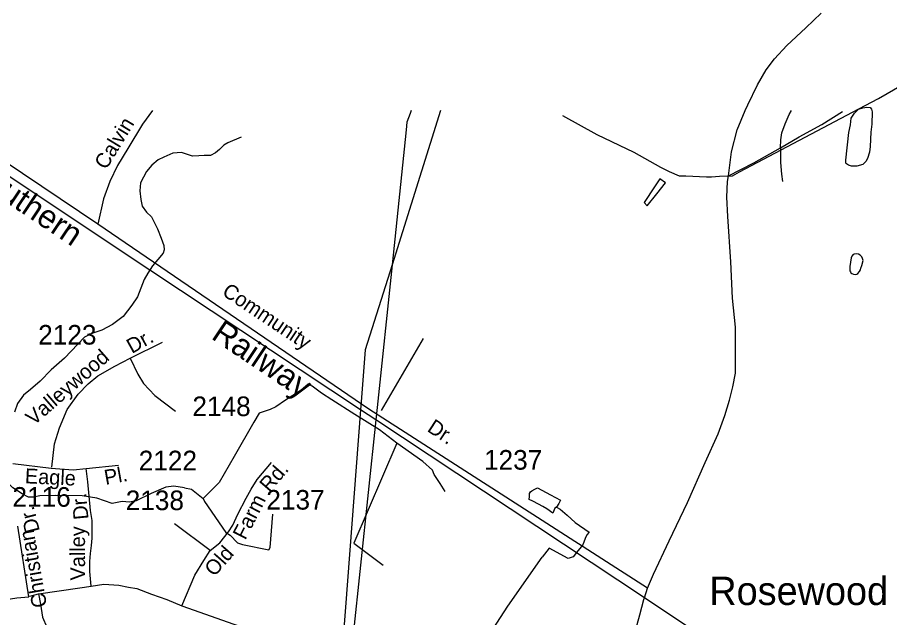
# Model space of a CAD drawing. Extents: x 2260773 to 2342389, y 552869 to 618546.
# Drawn here: x 2273078 to 2278640, y 607521 to 611347 of the extents above; entities that cross this region are included whole.
import ezdxf

# ---------------------------------------------------------------- set-up
doc = ezdxf.new("R2010")
doc.units = 0
for name, color, linetype in [('Exist Boundary Political Urban Extension UEB', 7, 'Continuous'), ('Exist Civil Demographics City Label', 7, 'Continuous'), ('Exist Hydrographic Creek Single Shore', 7, 'Continuous'), ('Exist Hydrographic Misc Water Feature', 7, 'Continuous'), ('Exist Railroad Mainline', 7, 'Continuous'), ('Exist Railroad Mainline Label', 7, 'Continuous'), ('Exist Road Non-System Type 51', 7, 'Continuous'), ('Exist Road Non-System Type 51 Label', 7, 'Continuous'), ('Exist Road Primary NC Attributed', 7, 'Continuous'), ('Exist Road Secondary Type 51 Attributed', 7, 'Continuous'), ('Exist Road Secondary Type 51 Label', 7, 'Continuous'), ('Exist Road Secondary Type 51 Number Label', 7, 'Continuous'), ('Exist Utilities Electrical Transmission Line', 7, 'Continuous')]:
    doc.layers.add(name, color=color, linetype=linetype)

msp = doc.modelspace()

# ---------------------------------------------------------------- linework, layer by layer
at = {"layer": 'Exist Boundary Political Urban Extension UEB'}
for p, q in [((2275776.6, 610753.3), (2275466.5, 609770.2)), ((2275272.2, 608924.2), (2275266.2, 608845.4)), ((2275266.2, 608845.4), (2275143.8, 607237.3))]:
    msp.add_line(p, q, dxfattribs=at)
msp.add_lwpolyline([(2275466.5, 609770.2), (2275295.2, 609227.4), (2275272.2, 608924.2)], dxfattribs=at)
at = {"layer": 'Exist Hydrographic Creek Single Shore'}
msp.add_lwpolyline([(2275482.5, 602914), (2275367.6, 603398.5), (2275023.5, 604563.1), (2274947.7, 604653.2), (2274904.6, 604854.2), (2274802.5, 605059.5), (2274800.7, 605269.5), (2274932.5, 605453.7), (2275188.6, 605665), (2275493.5, 605990.1), (2275598.7, 606128.4), (2275699.6, 606261.3), (2275813.6, 606485.4), (2275951.6, 606863), (2276114.1, 607114.1), (2276154, 607168.5), (2276008.9, 607270.2), (2276088.7, 607411.7), (2276204.8, 607593.2), (2276424.7, 607906.1)], dxfattribs=at)
at = {"layer": 'Exist Hydrographic Misc Water Feature'}
for points in [[(2276553, 610722.8), (2276773.8, 610600.4), (2277009.5, 610487), (2277179.5, 610391.4), (2277233.2, 610364.6), (2277298.9, 610337.7), (2277340.7, 610337.7), (2277471.9, 610331.7), (2277504.7, 610331.7), (2277555.5, 610334.7), (2277639, 610337.7), (2277683.8, 610361.6), (2278444.3, 610764.2), (2278569.1, 610830.5), (2278720.4, 610917.5), (2278843.3, 610982.2), (2278967.3, 611016.2), (2279168.5, 611094.2), (2279279.8, 611127.3), (2279387.7, 611162.2), (2279421.1, 611174.5)], [(2278521.1, 610616.2), (2278515.5, 610524.1), (2278512, 610488.2), (2278498.7, 610448), (2278488.9, 610428), (2278469, 610409.9), (2278431, 610399.4), (2278397, 610399.2), (2278377.1, 610404.7), (2278364.6, 610414.6), (2278360.7, 610418.5), (2278360.7, 610436.7), (2278381, 610612.5), (2278390.2, 610662.7), (2278396, 610704.7), (2278415.9, 610737), (2278441.5, 610761.2), (2278469.6, 610771.5), (2278495.4, 610775.7), (2278515.5, 610771.9), (2278525.4, 610761.9), (2278529.7, 610744.2), (2278526.4, 610666), (2278521.1, 610616.2)], [(2274503.7, 610584.6), (2274420.3, 610547.7), (2274394, 610533.4), (2274366.4, 610505.1), (2274340.5, 610483), (2274308.5, 610466.8), (2274269, 610466.2), (2274234.5, 610464.1), (2274193.3, 610463.5), (2274123, 610485), (2274068.8, 610482.2), (2274011, 610455.6), (2273975.5, 610439.5), (2273933.7, 610405.2), (2273900.1, 610364.9), (2273862.7, 610292.7), (2273859.1, 610240.5), (2273863.8, 610186.7), (2273873.8, 610142.6), (2273900.7, 610104.8), (2273932.7, 610075.3), (2273971.2, 609999.8), (2273994, 609939.9), (2274010.2, 609892.1), (2274012.6, 609866.2), (2274006.9, 609844.3), (2273973.5, 609803.9), (2273939.4, 609763.6), (2273908.1, 609717.3), (2273886.5, 609675.1), (2273843.5, 609564.8), (2273808, 609512.6), (2273751, 609440), (2273683.3, 609389.4), (2273615.7, 609352.9), (2273551.9, 609332.2), (2273504.5, 609307.7), (2273377.8, 609174.7), (2273292.3, 609099.9), (2273223.2, 609027.2), (2273161.3, 608974.5), (2273115.7, 608938.4), (2273078, 608886.1), (2273058.9, 608829.7)], [(2277075.5, 610167.9), (2277093.9, 610146.1), (2277155.3, 610222.8), (2277210.6, 610293.2), (2277174.3, 610316.9), (2277140.7, 610266.4), (2277075.5, 610167.9)], [(2278463.4, 609765), (2278471.1, 609797.1), (2278466.6, 609810.8), (2278462.7, 609821.1), (2278452.5, 609830.7), (2278440.8, 609836.6), (2278426.4, 609840.3), (2278414.8, 609838.5), (2278406.8, 609834.4), (2278398.8, 609824.2), (2278395.1, 609814.3), (2278387.3, 609758.3), (2278385.4, 609744.3), (2278385.6, 609732.2), (2278389.7, 609724.2), (2278391.8, 609718.2), (2278399.6, 609714.2), (2278410, 609710.6), (2278421.5, 609708.5), (2278431.8, 609710.6), (2278437.9, 609714.5), (2278447.6, 609726.8), (2278453.5, 609736.9), (2278457.6, 609748.9), (2278463.4, 609765)], [(2275804.9, 608324.2), (2275772.6, 608375.4), (2275748.6, 608413), (2275735.3, 608433.4), (2275724.7, 608460.9), (2275663.1, 608515.7), (2275496.2, 608633.4), (2275386.9, 608717.8), (2275229.8, 608816.1), (2275082.8, 608908.8), (2275017, 608952), (2274956.3, 608995.6), (2274931.3, 609008.4), (2274886.9, 608970.8), (2274787.7, 608905.8), (2274726.1, 608864.7), (2274688.5, 608847.6), (2274620.1, 608823.6), (2274585.7, 608766.1)], [(2274585.7, 608766.1), (2274459.4, 608546.5), (2274363.7, 608382.2), (2274261.1, 608279.6)], [(2275496.2, 608633.4), (2275222, 607995.6), (2275410.1, 607855.3)], [(2274143, 608347.3), (2274075.2, 608357.8), (2274023.1, 608352.5), (2273929.4, 608310.8), (2273835.6, 608263.9), (2273792.3, 608256.5), (2273745.6, 608259.9), (2273681.5, 608247.8), (2273584.6, 608280.7), (2273489.4, 608296.3), (2273322, 608298.6), (2273219.9, 608297.4), (2273180.3, 608287.1), (2273148.3, 608289.1), (2273107.7, 608308.6), (2273047.7, 608348.1), (2273019.6, 608375.8), (2272982.7, 608415.4), (2272946.6, 608433), (2272930.4, 608440.7)], [(2276506, 608217.6), (2276491.2, 608186.5), (2276454.2, 608213.2), (2276429, 608228), (2276400.8, 608244.3), (2276365.3, 608262.1), (2276341.5, 608274), (2276343, 608291.8), (2276343, 608311), (2276350.4, 608321.4), (2276359.3, 608328.8), (2276377.1, 608339.2), (2276394.9, 608348.1), (2276476.4, 608303.6), (2276541.6, 608268), (2276529.7, 608248.8), (2276514.9, 608225), (2276506, 608217.6)], [(2274143, 608347.3), (2274187.5, 608339.5), (2274261.1, 608279.6), (2274269.6, 608260.8), (2274406.4, 608062.3), (2274433.8, 608045.2), (2274481.6, 607997.3), (2274512.4, 607987), (2274680, 607952.8), (2274690.2, 607966.5), (2274707.3, 608178.7)], [(2276514.9, 608225), (2276538.9, 608210.8), (2276583.6, 608173.3), (2276633.8, 608127.6), (2276723.5, 608065.1), (2276709, 608046.9), (2276698.6, 608024.5), (2276682.6, 607984.4), (2276643, 607936), (2276621.3, 607907.7), (2276589.3, 607898.1), (2276469.6, 607963.5), (2276424.7, 607906.1)]]:
    msp.add_lwpolyline(points, dxfattribs=at)
at = {"layer": 'Exist Railroad Mainline'}
for points in [[(2277075.8, 607647), (2275362.6, 608781.5), (2275266.2, 608845.4), (2273928.2, 609731.4), (2272391.5, 610753.3), (2270229, 612191.5), (2265356.3, 615416.5), (2265047.6, 615620.9), (2265047, 615621.2)], [(2279466.6, 606053.8), (2278731.4, 606546.2), (2277092, 607636.3), (2277075.8, 607647)]]:
    msp.add_lwpolyline(points, dxfattribs=at)
at = {"layer": 'Exist Road Non-System Type 51'}
msp.add_line((2275665.1, 609300.1), (2275397.7, 608841.7), dxfattribs=at)
for points in [[(2273939.3, 610753.3), (2273875.5, 610666.5), (2273780.9, 610511.7), (2273716, 610403.1), (2273666.9, 610300.7), (2273626.1, 610190.4), (2273590.4, 610029)], [(2277943.7, 610516.5), (2277945.7, 610566), (2277953.6, 610611.4), (2277973.3, 610668.8), (2277999, 610728.1), (2278015.4, 610753.3)], [(2277943.7, 610516.5), (2278064.3, 610585.7), (2278208.5, 610664.8), (2278339, 610747.9)], [(2277611.8, 610337.6), (2277773.7, 610419.6), (2277943.7, 610516.5)], [(2277943.7, 610516.5), (2277943.7, 610421.6), (2277951.6, 610348.4), (2277957.5, 610301)]]:
    msp.add_lwpolyline(points, dxfattribs=at)
at = {"layer": 'Exist Road Primary NC Attributed'}
msp.add_line((2277075.8, 607647), (2277096.7, 607707.3), dxfattribs=at)
for points in [[(2277096.7, 607707.3), (2277134.6, 607796.6), (2277234.5, 608009.4), (2277350.1, 608254.4), (2277463.6, 608509.2), (2277545.9, 608691.9), (2277588.8, 608808.4), (2277619.8, 608906.5), (2277641.1, 608990.6), (2277658.3, 609078.9), (2277657.3, 609180.8), (2277658.1, 609372.5), (2277637.8, 609556.3), (2277628.4, 609787.8), (2277608.7, 610078.5), (2277602.7, 610201.1), (2277606.7, 610300), (2277611.8, 610337.6), (2277632.4, 610489.8), (2277668, 610630.2), (2277719.6, 610753.3), (2277735.2, 610790.4), (2277798.4, 610917), (2277851.8, 611011.9), (2277906.1, 611082.1), (2277984.2, 611168.1), (2278104.8, 611280.9), (2278203.6, 611373.8)], [(2276853.2, 606686.5), (2276918.2, 606993), (2276968.2, 607201.3), (2277014.1, 607415.5), (2277047, 607537.8), (2277072, 607636.1), (2277075.8, 607647)]]:
    msp.add_lwpolyline(points, dxfattribs=at)
at = {"layer": 'Exist Road Secondary Type 51 Attributed'}
for p, q in [((2273048.2, 608502.9), (2273293.2, 608473)), ((2273514.8, 608469.9), (2273721, 608491.5)), ((2273150.4, 607653), (2273079.5, 608103.3)), ((2274306.8, 607947.4), (2274079.1, 608117.2)), ((2273156.5, 607656), (2273212.8, 607671.9))]:
    msp.add_line(p, q, dxfattribs=at)
for points in [[(2277096.7, 607707.3), (2275318.8, 608849.9), (2273590.4, 610029), (2272510.7, 610753.3), (2271787.3, 611238.6), (2271619.8, 611340.2), (2271528.9, 611405.5)], [(2273795.5, 609174), (2274002.5, 609277.5)], [(2273296, 608480), (2273313, 608627.7), (2273345.1, 608730.2), (2273394.2, 608846.4), (2273465.6, 608944.7), (2273528.1, 609011.7), (2273590.6, 609060.8), (2273697.8, 609123.4), (2273795.5, 609174)], [(2273795.5, 609174), (2273846.3, 609072.2), (2273882.2, 609012.3), (2273954.2, 608937.1), (2274086, 608835.8)], [(2273293.2, 608473), (2273433.4, 608462), (2273514.8, 608469.9)], [(2273547.5, 607721.1), (2273539, 607813.8), (2273539, 607877), (2273543.4, 607928.7), (2273548.8, 607980.7), (2273553.8, 608027.3), (2273554.8, 608061.1), (2273553.8, 608138.4), (2273543.3, 608202.1), (2273526, 608386.9), (2273514.8, 608469.9)], [(2274306.8, 607947.4), (2274369.3, 607996.6), (2274422.9, 608068.1), (2274451.1, 608109.4), (2274483.6, 608179.8), (2274536, 608282), (2274567.4, 608339.6), (2274606.7, 608399.9), (2274698.3, 608509.9)], [(2274125.2, 607595.5), (2274208.5, 607791.1), (2274266.6, 607884.9), (2274306.8, 607947.4)], [(2273212.8, 607671.9), (2273475.8, 607709.2), (2273547.5, 607721.1)], [(2273547.5, 607721.1), (2273628.4, 607733.1), (2273723.2, 607727.7), (2273786.9, 607713.5), (2273838.1, 607704.8), (2273932.9, 607668.9), (2274029.9, 607635.1), (2274125.2, 607595.5)], [(2272621.5, 607592.6), (2272732.1, 607604.6), (2272814.3, 607610.6), (2272892.1, 607618), (2273073, 607646.5), (2273150.4, 607653)], [(2273212.8, 607671.9), (2273224, 607606.8), (2273237.4, 607523.8), (2273264.3, 607458.7), (2273295.7, 607404.9), (2273338.4, 607369), (2273459.4, 607294.9), (2273647.8, 607198.5), (2273883.3, 607075), (2274116.5, 606944.9), (2274356.5, 606801.3)], [(2274125.2, 607595.5), (2275085.3, 607256.8), (2275143.8, 607237.3), (2275198.4, 607219.1), (2275233.3, 607207.4), (2275596.6, 607088.5), (2275914.8, 606983.4), (2276137.4, 606917.7), (2276364, 606843.7), (2276572.4, 606777.7), (2276853.2, 606686.5)]]:
    msp.add_lwpolyline(points, dxfattribs=at)
at = {"layer": 'Exist Utilities Electrical Transmission Line'}
for p, q in [((2275466.5, 609770.2), (2275370.8, 608859.4)), ((2275370.8, 608859.4), (2275362.6, 608781.5)), ((2275362.6, 608781.5), (2275198.4, 607219.1))]:
    msp.add_line(p, q, dxfattribs=at)
msp.add_lwpolyline([(2275588.8, 610753.3), (2275581.7, 610734.5), (2275560.4, 610678.3), (2275556.8, 610630.2), (2275466.5, 609770.2)], dxfattribs=at)

# ---------------------------------------------------------------- texts
at = {"layer": 'Exist Civil Demographics City Label'}
msp.add_text('Rosewood', height=180.45, dxfattribs=at).set_placement((2277490.2, 607600.5))
at = {"layer": 'Exist Railroad Mainline Label'}
for s, p in [('Southern', (2272751.7, 610336.1)), ('Railway', (2274307.2, 609303))]:
    msp.add_text(s, height=150, rotation=326.1892, dxfattribs=at).set_placement(p)
at = {"layer": 'Exist Road Non-System Type 51 Label'}
msp.add_text('Calvin', height=95, rotation=58.6811, dxfattribs=at).set_placement((2273643.2, 610370.9))
at = {"layer": 'Exist Road Secondary Type 51 Label'}
for s, rotation, p in [('Community', 326.3362, (2274376.2, 609581.2)), ('Dr.', 28.9239, (2273807.1, 609200.9)), ('Valleywood', 41.1134, (2273181.6, 608740.7)), ('Dr.', 326.7374, (2275685, 608712.1)), ('Eagle', 357.2136, (2273123.3, 608376.9)), ('Pl.', 10.1593, (2273639.9, 608366.1)), ('Rd.', 49.1017, (2274684.4, 608314.1)), ('Dr.', 95.4457, (2273531.3, 608148.8)), ('Farm', 62.9826, (2274530.8, 608010.3)), ('Dr.', 104.1996, (2273221.3, 608073.1)), ('Christian', 99.9678, (2273267, 607592.3)), ('Valley', 90.1974, (2273509.4, 607756.8)), ('Old', 48.6378, (2274333, 607776.7))]:
    msp.add_text(s, height=95, rotation=rotation, dxfattribs=at).set_placement(p)
at = {"layer": 'Exist Road Secondary Type 51 Number Label'}
for s, p in [('2123', (2273209.9, 609261)), ('2148', (2274193.3, 608805)), ('2122', (2273851, 608459.4)), ('1237', (2276053.1, 608463.6)), ('2116', (2273045.7, 608227.3)), ('2138', (2273767.8, 608205.4)), ('2137', (2274664.8, 608208.8))]:
    msp.add_text(s, height=125, dxfattribs=at).set_placement(p)

doc.saveas('drawing.dxf')
